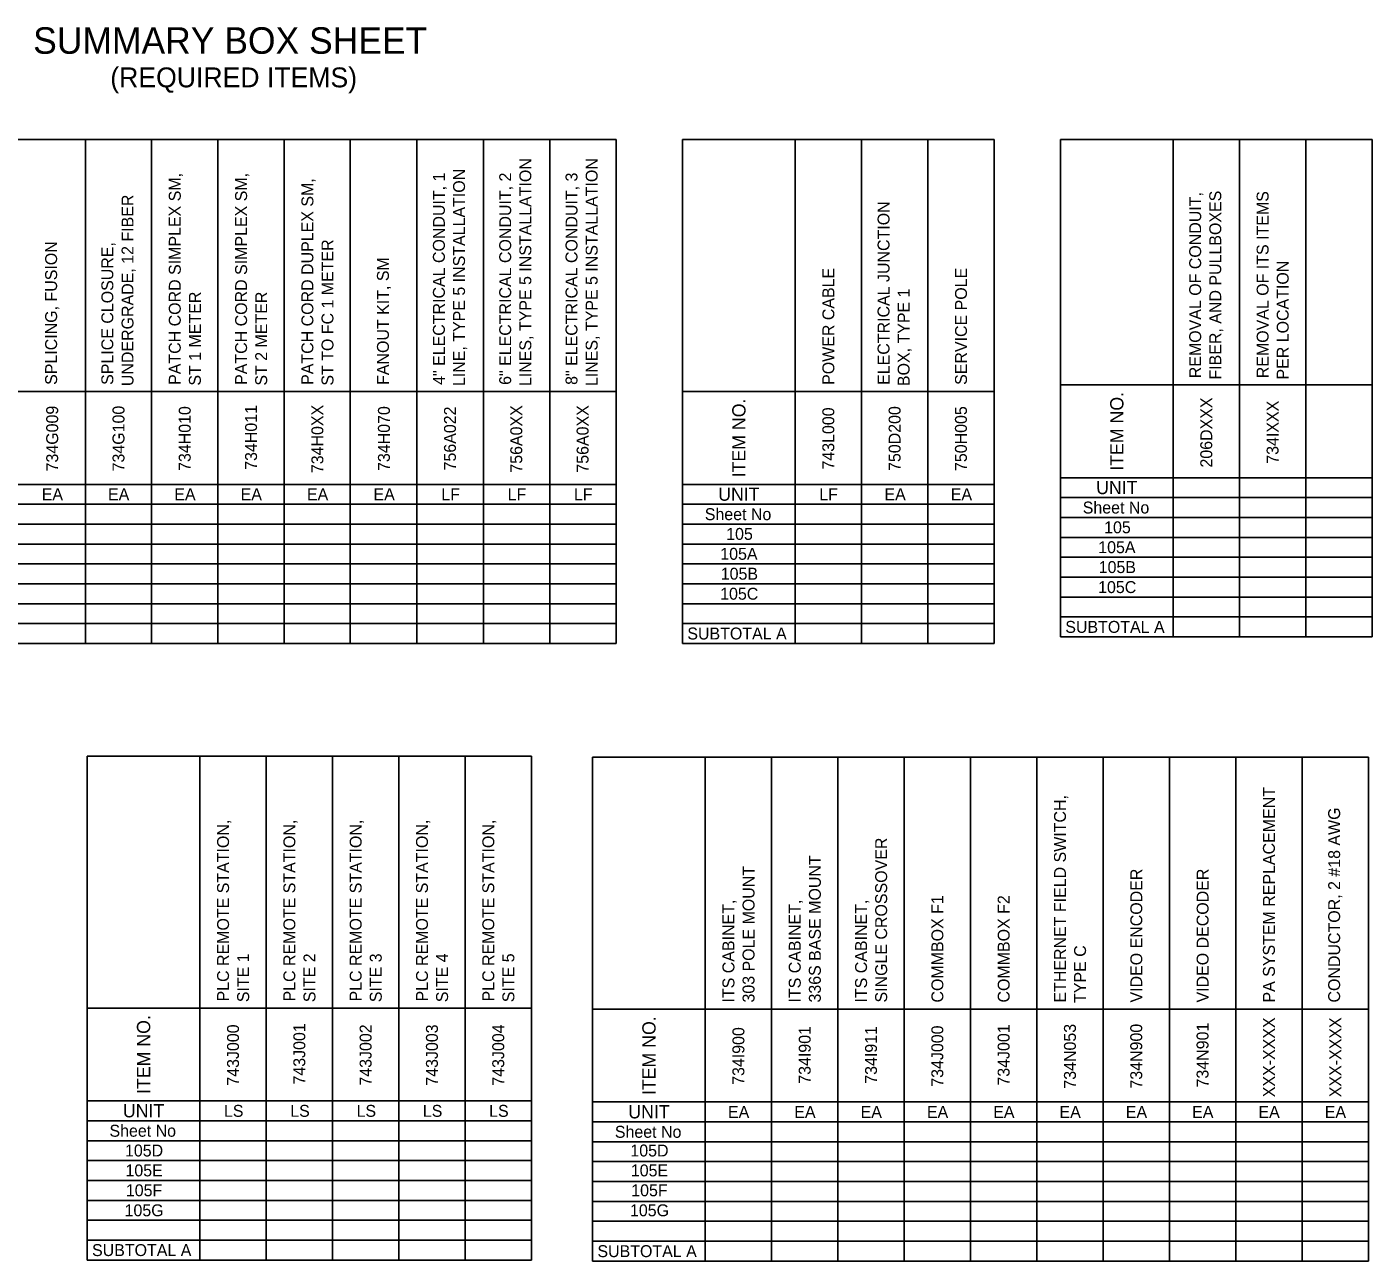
# Model space of a CAD drawing. Extents: x 5.9 to 40, y 1.1 to 19.8.
# Drawn here: x 19.72 to 40.01, y 1.15 to 19.77 of the extents above; entities that cross this region are included whole.
import ezdxf

# ---------------------------------------------------------------- set-up
doc = ezdxf.new("R2010")
doc.units = 0

msp = doc.modelspace()

# ---------------------------------------------------------------- linework, layer by layer
for p, q in [((5.905, 18.066), (28.611, 18.066)), ((20.605, 14.266), (20.605, 18.066)), ((21.605, 14.266), (21.605, 18.066)), ((22.605, 14.266), (22.605, 18.066)), ((23.605, 14.266), (23.605, 18.066)), ((24.601, 14.266), (24.601, 18.066)), ((25.605, 14.266), (25.605, 18.066)), ((26.611, 14.266), (26.611, 18.066)), ((27.611, 14.266), (27.611, 18.066)), ((28.611, 14.266), (28.611, 18.066)), ((29.611, 18.066), (34.311, 18.066)), ((29.611, 14.266), (29.611, 18.066)), ((31.311, 14.266), (31.311, 18.066)), ((32.311, 14.266), (32.311, 18.066)), ((33.311, 14.266), (33.311, 18.066)), ((34.311, 14.266), (34.311, 18.066)), ((35.311, 18.066), (40.011, 18.066)), ((35.311, 14.366), (35.311, 18.066)), ((37.011, 14.366), (37.011, 18.066)), ((38.011, 14.366), (38.011, 18.066)), ((39.011, 14.366), (39.011, 18.066)), ((40.011, 14.366), (40.011, 18.066)), ((5.905, 14.266), (28.611, 14.266)), ((20.605, 14.266), (20.605, 12.866)), ((21.605, 14.266), (21.605, 12.866)), ((22.605, 14.266), (22.605, 12.866)), ((23.605, 14.266), (23.605, 12.866)), ((24.601, 14.266), (24.601, 12.866)), ((25.605, 14.266), (25.605, 12.866)), ((26.611, 14.266), (26.611, 12.866)), ((27.611, 14.266), (27.611, 12.866)), ((28.611, 14.266), (28.611, 12.866)), ((29.611, 14.266), (34.311, 14.266)), ((29.611, 14.266), (29.611, 12.866)), ((31.311, 14.266), (31.311, 12.866)), ((32.311, 14.266), (32.311, 12.866)), ((33.311, 14.266), (33.311, 12.866)), ((34.311, 14.266), (34.311, 12.866)), ((35.311, 14.366), (40.011, 14.366)), ((35.311, 14.366), (35.311, 12.966)), ((37.011, 14.366), (37.011, 12.966)), ((38.011, 14.366), (38.011, 12.966)), ((39.011, 14.366), (39.011, 12.966)), ((40.011, 14.366), (40.011, 12.966)), ((5.905, 12.866), (28.611, 12.866)), ((20.605, 12.866), (20.605, 10.466)), ((21.605, 12.866), (21.605, 10.466)), ((22.605, 12.866), (22.605, 10.466)), ((23.605, 12.866), (23.605, 10.466)), ((24.601, 12.866), (24.601, 10.466)), ((25.605, 12.866), (25.605, 10.466)), ((26.611, 12.866), (26.611, 10.466)), ((27.611, 12.866), (27.611, 10.466)), ((28.611, 12.866), (28.611, 10.466)), ((29.611, 12.866), (34.311, 12.866)), ((29.611, 12.866), (29.611, 10.466)), ((31.311, 12.866), (31.311, 10.466)), ((32.311, 12.866), (32.311, 10.466)), ((33.311, 12.866), (33.311, 10.466)), ((34.311, 12.866), (34.311, 10.466)), ((35.311, 12.966), (40.011, 12.966)), ((35.311, 12.966), (35.311, 10.566)), ((37.011, 12.966), (37.011, 10.566)), ((38.011, 12.966), (38.011, 10.566)), ((39.011, 12.966), (39.011, 10.566)), ((40.011, 12.966), (40.011, 10.566)), ((35.311, 12.666), (40.011, 12.666)), ((5.905, 12.566), (28.611, 12.566)), ((29.611, 12.566), (34.311, 12.566)), ((5.905, 12.266), (28.611, 12.266)), ((29.611, 12.266), (34.311, 12.266)), ((35.311, 12.366), (40.011, 12.366)), ((35.311, 12.066), (40.011, 12.066)), ((5.905, 11.966), (28.611, 11.966)), ((29.611, 11.966), (34.311, 11.966)), ((5.905, 11.666), (28.611, 11.666)), ((29.611, 11.666), (34.311, 11.666)), ((35.311, 11.766), (40.011, 11.766)), ((5.905, 11.366), (28.611, 11.366)), ((29.611, 11.366), (34.311, 11.366)), ((35.311, 11.466), (40.011, 11.466)), ((35.311, 11.166), (40.011, 11.166)), ((5.905, 11.066), (28.611, 11.066)), ((29.611, 11.066), (34.311, 11.066)), ((5.905, 10.766), (28.611, 10.766)), ((29.611, 10.766), (34.311, 10.766)), ((35.311, 10.866), (40.011, 10.866)), ((35.311, 10.566), (40.011, 10.566)), ((5.905, 10.466), (28.611, 10.466)), ((29.611, 10.466), (34.311, 10.466)), ((20.633, 8.766), (27.333, 8.766)), ((20.633, 4.966), (20.633, 8.766)), ((22.333, 4.966), (22.333, 8.766)), ((23.333, 4.966), (23.333, 8.766)), ((24.333, 4.966), (24.333, 8.766)), ((25.333, 4.966), (25.333, 8.766)), ((26.333, 4.966), (26.333, 8.766)), ((27.333, 4.966), (27.333, 8.766)), ((28.255, 8.75), (39.955, 8.75)), ((28.255, 4.95), (28.255, 8.75)), ((29.955, 4.95), (29.955, 8.75)), ((30.955, 4.95), (30.955, 8.75)), ((31.955, 4.95), (31.955, 8.75)), ((32.955, 4.95), (32.955, 8.75)), ((33.955, 4.95), (33.955, 8.75)), ((34.955, 4.95), (34.955, 8.75)), ((35.955, 4.95), (35.955, 8.75)), ((35.955, 4.95), (35.955, 8.75)), ((36.955, 4.95), (36.955, 8.75)), ((37.955, 4.95), (37.955, 8.75)), ((38.955, 4.95), (38.955, 8.75)), ((39.955, 4.95), (39.955, 8.75)), ((20.633, 4.966), (27.333, 4.966)), ((20.633, 4.966), (20.633, 3.566)), ((22.333, 4.966), (22.333, 3.566)), ((23.333, 4.966), (23.333, 3.566)), ((24.333, 4.966), (24.333, 3.566)), ((25.333, 4.966), (25.333, 3.566)), ((26.333, 4.966), (26.333, 3.566)), ((27.333, 4.966), (27.333, 3.566)), ((28.255, 4.95), (39.955, 4.95)), ((28.255, 4.95), (28.255, 3.55)), ((29.955, 4.95), (29.955, 3.55)), ((30.955, 4.95), (30.955, 3.55)), ((31.955, 4.95), (31.955, 3.55)), ((32.955, 4.95), (32.955, 3.55)), ((33.955, 4.95), (33.955, 3.55)), ((34.955, 4.95), (34.955, 3.55)), ((35.955, 4.95), (35.955, 3.55)), ((36.955, 4.95), (36.955, 3.55)), ((37.955, 4.95), (37.955, 3.55)), ((38.955, 4.95), (38.955, 3.55)), ((39.955, 4.95), (39.955, 3.55)), ((20.633, 3.566), (27.333, 3.566)), ((20.633, 3.566), (20.633, 1.166)), ((22.333, 3.566), (22.333, 1.166)), ((23.333, 3.566), (23.333, 1.166)), ((24.333, 3.566), (24.333, 1.166)), ((25.333, 3.566), (25.333, 1.166)), ((26.333, 3.566), (26.333, 1.166)), ((27.333, 3.566), (27.333, 1.166)), ((28.255, 3.55), (39.955, 3.55)), ((28.255, 3.55), (28.255, 1.15)), ((29.955, 3.55), (29.955, 1.15)), ((30.955, 3.55), (30.955, 1.15)), ((31.955, 3.55), (31.955, 1.15)), ((32.955, 3.55), (32.955, 1.15)), ((33.955, 3.55), (33.955, 1.15)), ((34.955, 3.55), (34.955, 1.15)), ((35.955, 3.55), (35.955, 1.15)), ((36.955, 3.55), (36.955, 1.15)), ((37.955, 3.55), (37.955, 1.15)), ((38.955, 3.55), (38.955, 1.15)), ((39.955, 3.55), (39.955, 1.15)), ((20.633, 3.266), (27.333, 3.266)), ((28.255, 3.25), (39.955, 3.25)), ((20.633, 2.966), (27.333, 2.966)), ((28.255, 2.95), (39.955, 2.95)), ((20.633, 2.666), (27.333, 2.666)), ((28.255, 2.65), (39.955, 2.65)), ((20.633, 2.366), (27.333, 2.366)), ((28.255, 2.35), (39.955, 2.35)), ((20.633, 2.066), (27.333, 2.066)), ((28.255, 2.05), (39.955, 2.05)), ((20.633, 1.766), (27.333, 1.766)), ((28.255, 1.75), (39.955, 1.75)), ((20.633, 1.466), (27.333, 1.466)), ((28.255, 1.45), (39.955, 1.45)), ((20.633, 1.166), (27.333, 1.166)), ((28.255, 1.15), (39.955, 1.15))]:
    msp.add_line(p, q)

# ---------------------------------------------------------------- texts
for s, height, p in [('SUMMARY BOX SHEET', 0.4, (19.818, 19.36)), ('(REQUIRED ITEMS)', 0.3, (20.981, 18.854)), ('EA', 0.18, (19.947, 12.626)), ('EA', 0.18, (20.947, 12.626)), ('EA', 0.18, (21.947, 12.626)), ('EA', 0.18, (22.947, 12.626)), ('EA', 0.18, (23.947, 12.626)), ('EA', 0.18, (24.951, 12.626)), ('LF', 0.18, (25.974, 12.626)), ('LF', 0.18, (26.974, 12.626)), ('LF', 0.18, (27.974, 12.626)), ('LF', 0.18, (31.674, 12.626)), ('EA', 0.18, (32.657, 12.626)), ('EA', 0.18, (33.657, 12.626)), ('105', 0.18, (30.27, 12.028)), ('105', 0.18, (35.97, 12.128)), ('105A', 0.18, (35.881, 11.828)), ('105A', 0.18, (30.181, 11.728)), ('105B', 0.18, (30.188, 11.428)), ('105B', 0.18, (35.888, 11.528)), ('105C', 0.18, (35.879, 11.226)), ('105C', 0.18, (30.179, 11.126)), ('LS', 0.18, (22.695, 3.326)), ('LS', 0.18, (23.695, 3.326)), ('LS', 0.18, (24.695, 3.326)), ('LS', 0.18, (25.695, 3.326)), ('LS', 0.18, (26.695, 3.326)), ('EA', 0.18, (30.297, 3.31)), ('EA', 0.18, (31.297, 3.31)), ('EA', 0.18, (32.297, 3.31)), ('EA', 0.18, (33.297, 3.31)), ('EA', 0.18, (34.297, 3.31)), ('EA', 0.18, (35.297, 3.31)), ('EA', 0.18, (36.297, 3.31)), ('EA', 0.18, (37.297, 3.31)), ('EA', 0.18, (38.297, 3.31)), ('EA', 0.18, (39.297, 3.31)), ('105D', 0.18, (21.203, 2.728)), ('105D', 0.18, (28.825, 2.728)), ('105E', 0.18, (21.21, 2.428)), ('105E', 0.18, (28.832, 2.428)), ('105F', 0.18, (21.216, 2.128)), ('105F', 0.18, (28.838, 2.128)), ('105G', 0.18, (21.197, 1.826)), ('105G', 0.18, (28.819, 1.826))]:
    msp.add_text(s, height=height).set_placement(p)
for s, height, rotation, p in [('LINES, TYPE 5 INSTALLATION', 0.18, 90, (27.331, 14.348)), ('LINES, TYPE 5 INSTALLATION', 0.18, 90, (28.331, 14.348)), ('PATCH CORD SIMPLEX SM, ', 0.18, 90, (22.044, 14.366)), ('PATCH CORD SIMPLEX SM, ', 0.18, 90, (23.044, 14.366)), ('PATCH CORD DUPLEX SM, ', 0.18, 90, (24.044, 14.366)), ('4" ELECTRICAL CONDUIT, 1 ', 0.18, 90, (26.027, 14.366)), ('LINE, TYPE 5 INSTALLATION', 0.18, 90, (26.331, 14.348)), ('6" ELECTRICAL CONDUIT, 2 ', 0.18, 90, (27.027, 14.366)), ('8" ELECTRICAL CONDUIT, 3 ', 0.18, 90, (28.027, 14.366)), ('REMOVAL OF CONDUIT, ', 0.18, 90, (37.433, 14.466)), ('FIBER, AND PULLBOXES', 0.18, 90, (37.736, 14.446)), ('REMOVAL OF ITS ITEMS ', 0.18, 90, (38.45, 14.466)), ('UNDERGRADE, 12 FIBER', 0.18, 90, (21.331, 14.347)), ('ELECTRICAL JUNCTION ', 0.18, 90, (32.733, 14.366)), ('SPLICING, FUSION', 0.18, 90, (20.179, 14.366)), ('SPLICE CLOSURE, ', 0.18, 90, (21.027, 14.366)), ('ST TO FC 1 METER', 0.18, 90, (24.347, 14.355)), ('FANOUT KIT, SM', 0.18, 90, (25.183, 14.366)), ('POWER CABLE', 0.18, 90, (31.901, 14.366)), ('SERVICE POLE', 0.18, 90, (33.901, 14.366)), ('PER LOCATION', 0.18, 90, (38.753, 14.447)), ('ST 1 METER', 0.18, 90, (22.347, 14.355)), ('ST 2 METER', 0.18, 90, (23.347, 14.355)), ('BOX, TYPE 1', 0.18, 90, (33.036, 14.348)), ('ITEM NO.', 0.2, 90, (36.261, 13.071)), ('734G009', 0.18, 90, (20.195, 13.061)), ('734G100', 0.18, 90, (21.195, 13.061)), ('734H010', 0.18, 90, (22.194, 13.068)), ('734H011', 0.18, 90, (23.194, 13.085)), ('734H0XX', 0.18, 90, (24.194, 13.035)), ('734H070', 0.18, 90, (25.198, 13.068)), ('756A022', 0.18, 90, (26.194, 13.076)), ('756A0XX', 0.18, 90, (27.194, 13.042)), ('756A0XX', 0.18, 90, (28.194, 13.042)), ('ITEM NO.', 0.2, 90, (30.561, 12.971)), ('743L000', 0.18, 90, (31.9, 13.089)), ('750D200', 0.18, 90, (32.9, 13.068)), ('750H005', 0.18, 90, (33.9, 13.067)), ('206DXXX', 0.18, 90, (37.6, 13.119)), ('734IXXX', 0.18, 90, (38.6, 13.177)), ('UNIT', 0.2, 360, (30.149, 12.618)), ('UNIT', 0.2, 360, (35.849, 12.718)), ('Sheet No', 0.18, 360, (35.647, 12.426)), ('Sheet No', 0.18, 360, (29.947, 12.326)), ('SUBTOTAL A', 0.18, 360, (35.384, 10.626)), ('SUBTOTAL A', 0.18, 360, (29.684, 10.526)), ('ETHERNET FIELD SWITCH, ', 0.18, 90, (35.394, 5.05)), ('PA SYSTEM REPLACEMENT', 0.18, 90, (38.545, 5.05)), ('CONDUCTOR, 2 #18 AWG', 0.18, 90, (39.529, 5.05)), ('PLC REMOTE STATION, ', 0.18, 90, (22.772, 5.066)), ('PLC REMOTE STATION, ', 0.18, 90, (23.772, 5.066)), ('PLC REMOTE STATION, ', 0.18, 90, (24.772, 5.066)), ('PLC REMOTE STATION, ', 0.18, 90, (25.772, 5.066)), ('PLC REMOTE STATION, ', 0.18, 90, (26.772, 5.066)), ('SINGLE CROSSOVER', 0.18, 90, (32.697, 5.05)), ('303 POLE MOUNT', 0.18, 90, (30.697, 5.05)), ('336S BASE MOUNT', 0.18, 90, (31.697, 5.05)), ('VIDEO ENCODER', 0.18, 90, (36.545, 5.05)), ('VIDEO DECODER', 0.18, 90, (37.545, 5.05)), ('ITS CABINET, ', 0.18, 90, (30.394, 5.05)), ('ITS CABINET, ', 0.18, 90, (31.394, 5.05)), ('ITS CABINET, ', 0.18, 90, (32.394, 5.05)), ('COMMBOX F1', 0.18, 90, (33.545, 5.05)), ('COMMBOX F2', 0.18, 90, (34.545, 5.05)), ('TYPE C', 0.18, 90, (35.697, 5.044)), ('SITE 1', 0.18, 90, (23.075, 5.055)), ('SITE 2', 0.18, 90, (24.075, 5.055)), ('SITE 3', 0.18, 90, (25.075, 5.055)), ('SITE 4', 0.18, 90, (26.075, 5.055)), ('SITE 5', 0.18, 90, (27.075, 5.055)), ('ITEM NO.', 0.2, 90, (21.583, 3.671)), ('743J000', 0.18, 90, (22.922, 3.796)), ('743J001', 0.18, 90, (23.922, 3.813)), ('743J002', 0.18, 90, (24.922, 3.797)), ('743J003', 0.18, 90, (25.922, 3.796)), ('743J004', 0.18, 90, (26.922, 3.796)), ('ITEM NO.', 0.2, 90, (29.205, 3.654)), ('734I900', 0.18, 90, (30.544, 3.808)), ('734I901', 0.18, 90, (31.544, 3.825)), ('734I911', 0.18, 90, (32.544, 3.825)), ('734J000', 0.18, 90, (33.544, 3.78)), ('734J001', 0.18, 90, (34.544, 3.797)), ('734N053', 0.18, 90, (35.544, 3.751)), ('734N900', 0.18, 90, (36.544, 3.752)), ('734N901', 0.18, 90, (37.544, 3.769)), ('XXX-XXXX', 0.18, 90, (38.545, 3.622)), ('XXX-XXXX', 0.18, 90, (39.545, 3.622)), ('UNIT', 0.2, 360, (21.171, 3.318)), ('UNIT', 0.2, 360, (28.793, 3.302)), ('Sheet No', 0.18, 360, (20.969, 3.026)), ('Sheet No', 0.18, 360, (28.591, 3.01)), ('SUBTOTAL A', 0.18, 360, (20.706, 1.226)), ('SUBTOTAL A', 0.18, 360, (28.328, 1.21))]:
    msp.add_text(s, height=height, rotation=rotation).set_placement(p)

doc.saveas('drawing.dxf')
